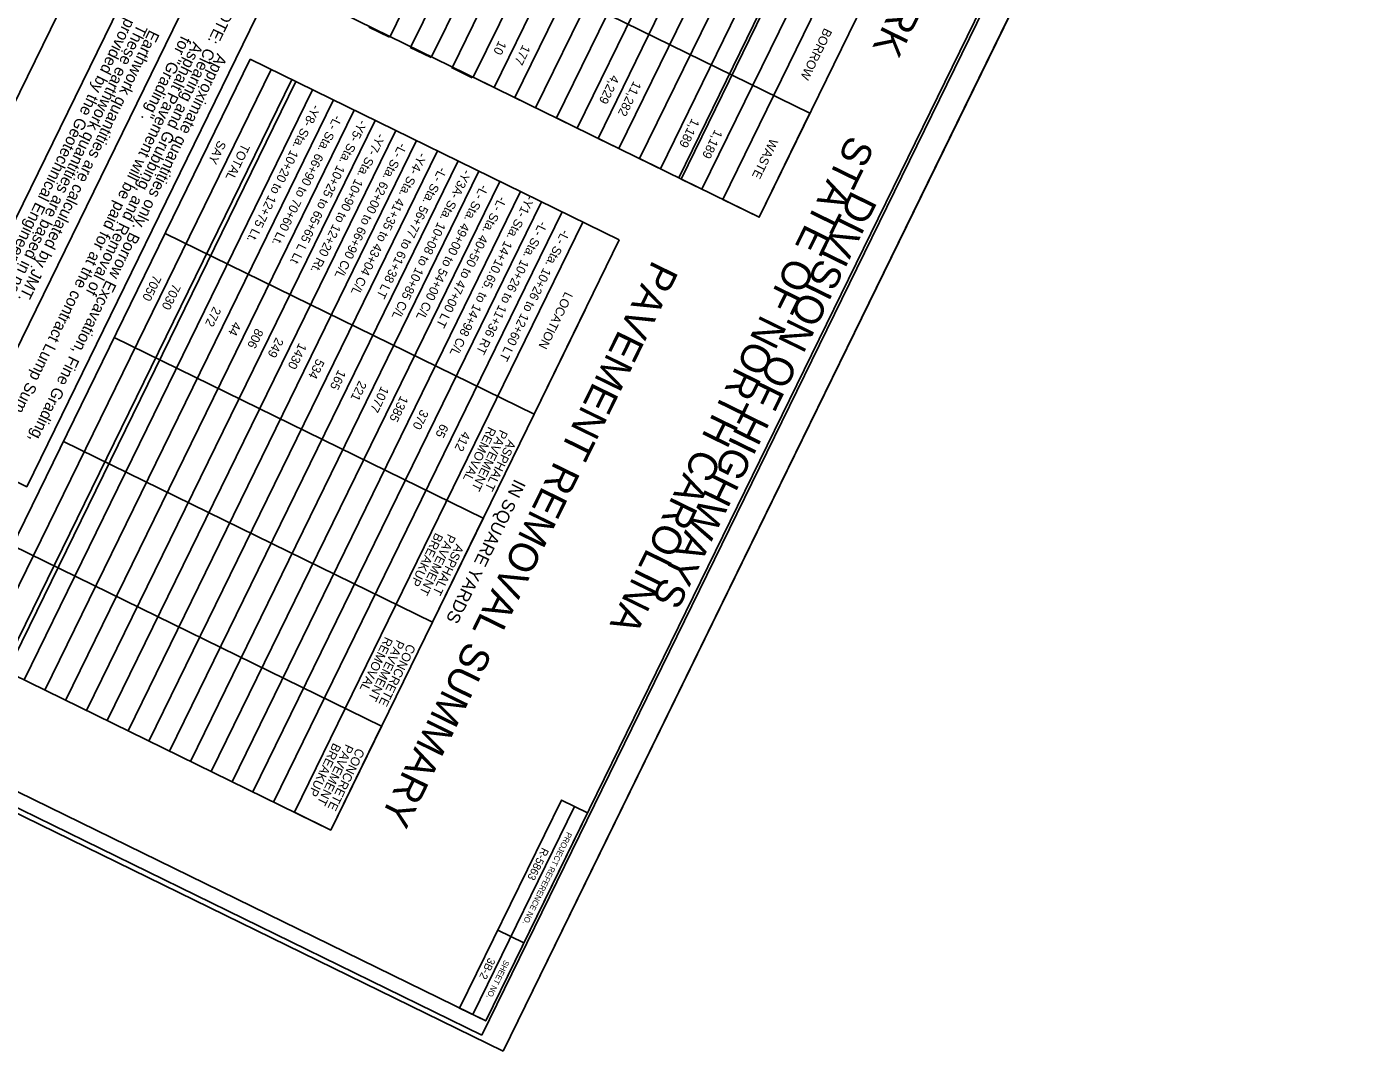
# Model space of a CAD drawing. Extents: x 1527431 to 1570373, y 611106 to 634616.
# Drawn here: x 1527683.1 to 1527913.4, y 634217 to 634394 of the extents above; entities that cross this region are included whole.
import ezdxf

# ---------------------------------------------------------------- set-up
doc = ezdxf.new("R2010")
doc.units = 0
for name, color, linetype in [('Sheet Cutting Line CELL', 7, 'Continuous'), ('Sheet Data Field CELL', 7, 'Continuous'), ('Sheet Plot Border Inside CELL', 7, 'Continuous'), ('Sheet Plot Border Outside CELL', 7, 'Continuous'), ('Sheet Summary Earthwork CELL', 7, 'Continuous')]:
    doc.layers.add(name, color=color, linetype=linetype)

msp = doc.modelspace()

# ---------------------------------------------------------------- linework, layer by layer
at = {"layer": 'Sheet Cutting Line CELL'}
msp.add_line((1527765.39, 634217.03), (1527913.36, 634519.58), dxfattribs=at)
at = {"layer": 'Sheet Plot Border Inside CELL'}
msp.add_lwpolyline([(1527761.75, 634219.81), (1527908.19, 634519.22), (1527718.63, 634611.93), (1527572.19, 634312.52)], close=True, dxfattribs=at)
at = {"layer": 'Sheet Plot Border Outside CELL'}
msp.add_lwpolyline([(1527765.39, 634217.03), (1527913.36, 634519.58), (1527715.73, 634616.24), (1527567.76, 634313.68)], close=True, dxfattribs=at)
at = {"layer": 'Sheet Summary Earthwork CELL'}
for p, q in [((1527745.86, 634392.32), (1527811.77, 634527.06)), ((1527815.36, 634525.31), (1527749.46, 634390.56)), ((1527753.05, 634388.8), (1527818.95, 634523.55)), ((1527822.55, 634521.79), (1527756.64, 634387.04)), ((1527760.24, 634385.29), (1527826.14, 634520.03)), ((1527829.73, 634518.28), (1527763.83, 634383.53)), ((1527767.42, 634381.77), (1527833.33, 634516.52)), ((1527836.92, 634514.76), (1527771.02, 634380.01)), ((1527774.61, 634378.26), (1527840.51, 634513)), ((1527844.11, 634511.25), (1527778.2, 634376.5)), ((1527781.8, 634374.74), (1527847.7, 634509.49)), ((1527851.29, 634507.73), (1527785.39, 634372.98)), ((1527788.98, 634371.23), (1527854.89, 634505.97)), ((1527858.48, 634504.22), (1527792.58, 634369.47)), ((1527795.75, 634367.92), (1527861.65, 634502.67)), ((1527796.17, 634367.71), (1527862.07, 634502.46)), ((1527865.67, 634500.7), (1527799.76, 634365.95)), ((1527689.83, 634399.03), (1527639.97, 634297.08)), ((1527745.77, 634392.21), (1527742.17, 634393.97)), ((1527721.7, 634388.4), (1527671.84, 634286.45)), ((1527721.7, 634388.4), (1527785.48, 634357.21)), ((1527752.95, 634388.7), (1527749.36, 634390.45)), ((1527725.29, 634386.64), (1527675.43, 634284.69)), ((1527760.06, 634385.2), (1527756.47, 634386.96)), ((1527728.89, 634384.88), (1527679.02, 634282.93)), ((1527729.58, 634384.55), (1527679.72, 634282.59)), ((1527763.83, 634383.53), (1527760.24, 634385.29)), ((1527732.48, 634383.13), (1527682.62, 634281.18)), ((1527736.07, 634381.37), (1527686.21, 634279.42)), ((1527771.02, 634380.01), (1527767.42, 634381.77)), ((1527739.67, 634379.61), (1527689.8, 634277.66)), ((1527743.26, 634377.85), (1527693.4, 634275.9)), ((1527778.2, 634376.5), (1527774.61, 634378.26)), ((1527746.85, 634376.1), (1527696.99, 634274.15)), ((1527750.45, 634374.34), (1527700.58, 634272.39)), ((1527785.39, 634372.98), (1527781.8, 634374.74)), ((1527754.04, 634372.58), (1527704.18, 634270.63)), ((1527707.77, 634268.87), (1527757.63, 634370.83)), ((1527792.58, 634369.47), (1527788.98, 634371.23)), ((1527761.23, 634369.07), (1527711.36, 634267.12)), ((1527799.76, 634365.95), (1527796.17, 634367.71)), ((1527714.96, 634265.36), (1527764.82, 634367.31)), ((1527768.41, 634365.55), (1527718.55, 634263.6)), ((1527722.14, 634261.84), (1527772.01, 634363.8)), ((1527775.6, 634362.04), (1527725.74, 634260.09)), ((1527770.77, 634327.12), (1527706.99, 634358.31)), ((1527785.48, 634357.21), (1527770.77, 634327.12)), ((1527777.72, 634259.32), (1527760.14, 634223.38)), ((1527768.98, 634235.76), (1527764.48, 634237.95))]:
    msp.add_line(p, q, dxfattribs=at)
for points in [[(1527762.39, 634222.28), (1527894.2, 634491.77), (1527705.55, 634584.04), (1527573.75, 634314.54)], [(1527713.27, 634403.66), (1527672.28, 634319.84), (1527663.24, 634324.26), (1527704.23, 634408.08)], [(1527724.07, 634398.38), (1527683.07, 634314.56), (1527672.28, 634319.84), (1527713.27, 634403.66)], [(1527779.97, 634258.22), (1527762.39, 634222.28), (1527757.89, 634224.48), (1527775.47, 634260.42)]]:
    msp.add_lwpolyline(points, close=True, dxfattribs=at)
for points in [[(1527707.56, 634578.03), (1527875.55, 634495.87), (1527809.65, 634361.12), (1527803.36, 634364.2), (1527869.26, 634498.95)], [(1527650.45, 634461.25), (1527818.43, 634379.09), (1527809.65, 634361.12), (1527641.66, 634443.28)], [(1527779.55, 634345.09), (1527735.62, 634255.25), (1527729.33, 634258.33), (1527779.19, 634360.28)], [(1527698.2, 634340.35), (1527761.98, 634309.15), (1527753.19, 634291.19), (1527689.41, 634322.38)], [(1527680.63, 634304.41), (1527744.41, 634273.22), (1527735.62, 634255.25), (1527671.84, 634286.45)]]:
    msp.add_lwpolyline(points, dxfattribs=at)

# ---------------------------------------------------------------- texts
at = {"layer": 'Sheet Data Field CELL'}
for s, p in [('R-5863', (1527772.15, 634252.32)), ('3B-2', (1527762.91, 634233.31))]:
    msp.add_text(s, height=1.35, rotation=243.9377, dxfattribs=at).set_placement(p)
at = {"layer": 'Sheet Summary Earthwork CELL'}
for s, height, p in [('SUMMARY OF EARTHWORK', 5, (1527868.99, 634471.86)), ('NOTE:', 2, (1527717.9, 634398.93)), ('provided by the Geotechnical Engineering Unit.', 2, (1527700.16, 634395.62)), ('These earthwork quantities are based in part on subsurface data ', 2, (1527702.23, 634394.61)), ('Earthwork quantities are calculated by JMT. ', 2, (1527704.3, 634393.6)), ('BORROW', 1.55, (1527820.92, 634393.91)), ('Asphalt Pavement will be paid for at the contract Lump Sum cost ', 2, (1527711.87, 634391.54)), ('for "Grading".', 2, (1527709.8, 634392.55)), ('10', 1.55, (1527764.67, 634391.71)), ('177', 1.55, (1527768.8, 634391)), ('Approximate quantities only. Borrow Excavation, Fine Grading, ', 2, (1527716, 634389.52)), ('Clearing and Grubbing, and Removal of ', 2, (1527713.93, 634390.53)), ('4,229', 1.55, (1527784.18, 634385.82)), ('11,282', 1.55, (1527787.97, 634384.73)), ('-Y8- Sta. 10+20 to 12+75 Lt.', 1.55, (1527732.54, 634380.71)), ('-L- Sta. 66+90 to 70+60 Lt.', 1.55, (1527736.27, 634378.89)), ('-Y5- Sta. 10+25 to 65+65 L Lt', 1.55, (1527740.58, 634378.09)), ('1,189', 1.55, (1527798.03, 634378.27)), ('SAY', 1.55, (1527716.21, 634374.5)), ('-Y7- Sta. 10+90 to 12+20 Rt.', 1.55, (1527743.7, 634375.73)), ('STATE OF NORTH CAROLINA', 4.9999, (1527825.21, 634375.52)), ('1,189', 1.55, (1527802.01, 634376.37)), ('WASTE', 1.55, (1527811.59, 634374.84)), ('TOTAL', 1.55, (1527720.31, 634373.94)), ('-L- Sta. 62+00 to 66+90 C/L', 1.55, (1527747.5, 634374.07)), ('-Y4- Sta. 41+35 to 43+04 C/L', 1.55, (1527750.92, 634372.42)), ('-L- Sta. 56+77 to 61+38 LT', 1.55, (1527754.4, 634369.9)), ('-Y3A- Sta. 10+08 to 10+85 C/L', 1.55, (1527758.6, 634369.49)), ('-L- Sta. 49+00 to 54+00 C/L', 1.55, (1527761.57, 634366.88)), ('DIVISION OF HIGHWAYS', 4.9999, (1527825.66, 634365.95)), ('-L- Sta. 40+50 to 47+00 LT', 1.55, (1527764.72, 634364.84)), ('-Y1- Sta. 14+10.65. to 14+98 C/L', 1.55, (1527769.53, 634365.02)), ('-L- Sta. 10+26 to 11+36 RT', 1.55, (1527771.77, 634360.54)), ('-L- Sta. 10+26 to 12+60 LT', 1.55, (1527775.62, 634359.1)), ('PAVEMENT REMOVAL SUMMARY', 5, (1527791.31, 634353.86)), ('7050', 1.55, (1527705.02, 634351.25)), ('7030', 1.55, (1527708.37, 634349.74)), ('LOCATION', 1.55, (1527776.12, 634348.34)), ('272', 1.55, (1527715.37, 634345.79)), ('44', 1.55, (1527718.85, 634343.19)), ('806', 1.55, (1527722.66, 634342.03)), ('249', 1.55, (1527726.16, 634340.44)), ('1430', 1.55, (1527730.15, 634339.48)), ('534', 1.55, (1527733.21, 634336.78)), ('165', 1.55, (1527736.94, 634334.87)), ('221', 1.55, (1527740.52, 634332.98)), ('1077', 1.55, (1527744.36, 634332.01)), ('1385', 1.55, (1527747.71, 634330.38)), ('370', 1.55, (1527751.21, 634328.02)), ('65', 1.55, (1527754.66, 634325.55)), ('412', 1.55, (1527758.48, 634324.26)), ('REMOVAL', 1.55, (1527762.88, 634325.04)), ('PAVEMENT', 1.55, (1527764.89, 634324.53)), ('ASPHALT', 1.55, (1527766.31, 634322.79)), ('IN SQUARE YARDS', 2.2, (1527767.41, 634316.02)), ('BREAKUP', 1.55, (1527753.72, 634306.71)), ('PAVEMENT', 1.55, (1527755.89, 634306.52)), ('ASPHALT', 1.55, (1527757.3, 634304.78)), ('REMOVAL', 1.55, (1527745.03, 634288.75)), ('PAVEMENT', 1.55, (1527747.04, 634288.23)), ('CONCRETE', 1.55, (1527748.96, 634287.54)), ('BREAKUP', 1.55, (1527736.07, 634270.41)), ('PAVEMENT', 1.55, (1527738.23, 634270.21)), ('CONCRETE', 1.55, (1527740.15, 634269.52)), ('PROJECT REFERENCE NO.', 1, (1527776.46, 634255)), ('SHEET NO.', 1, (1527765.62, 634232.88))]:
    msp.add_text(s, height=height, rotation=243.9377, dxfattribs=at).set_placement(p)

doc.saveas('drawing.dxf')
